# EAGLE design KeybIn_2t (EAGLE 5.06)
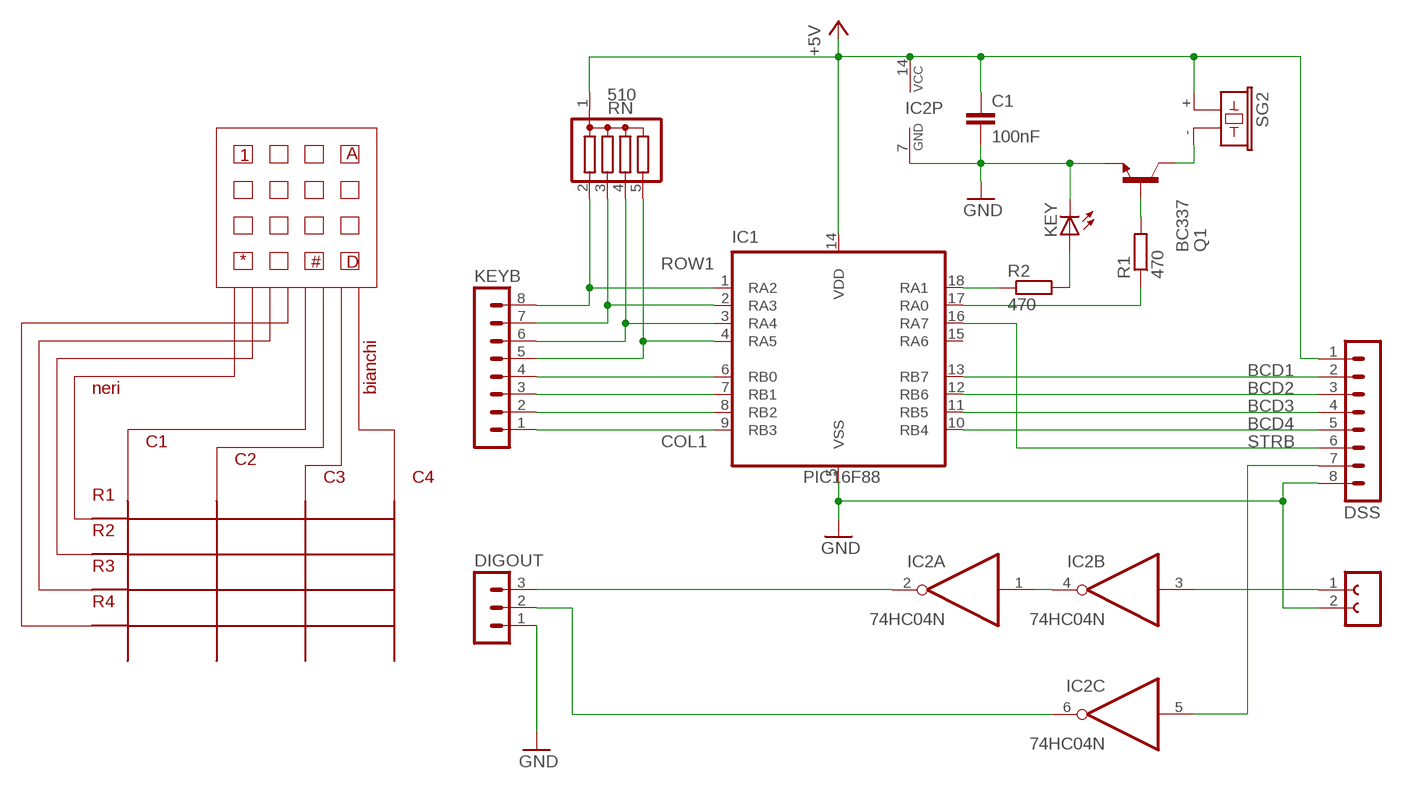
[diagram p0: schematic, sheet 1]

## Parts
510  RN  G04R  [SIL5]
C1  100nF  C-EU050-024X044  [C050-024X044]
DIGOUT  MA03-1  [MA03-1]
DSS  MA08-1  [MA08-1]
IC1  PIC16F88  [DIL18]
IC2  74HC04N  [DIL14]
KEY  LED3MM  [LED3MM]
KEYB  MA08-1  [MA08-1]
Q1  BC337  [TO92]
R1  470  R-EU_0204/7  [0204/7]
R2  470  R-EU_0204/7  [0204/7]
SG2  F/CM12P  [F/CM12P]
U$1  FE02-1  [FE-2]

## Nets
+5V: 510.1 C1.1 DSS.1 IC1.14(VDD) IC2.14(P:VCC) SG2.+
BCD1: DSS.2 IC1.13(RB7)
BCD2: DSS.3 IC1.12(RB6)
BCD3: DSS.4 IC1.11(RB5)
BCD4: DSS.5 IC1.10(RB4)
COL1: IC1.6(RB0) KEYB.4
DIG: DSS.8 IC1.5(VSS) U$1.2 ; supply symbol labelled GND
GND: C1.2 DIGOUT.1 IC2.7(P:GND) KEY.K(C) Q1.1(E)
N$1: IC1.17(RA0) R1.1
N$2: 510.3 IC1.2(RA3) KEYB.7
N$3: 510.4 IC1.3(RA4) KEYB.6
N$4: 510.5 IC1.4(RA5) KEYB.5
N$5: Q1.2(B) R1.2
N$6: IC1.9(RB3) KEYB.1
N$7: IC1.8(RB2) KEYB.2
N$8: IC1.7(RB1) KEYB.3
N$9: Q1.3(C) SG2.-
N$10: IC1.18(RA1) R2.1
N$11: IC2.1(A:I) IC2.4(B:O)
N$12: IC2.3(B:I) U$1.1
N$13: DIGOUT.3 IC2.2(A:O)
N$14: DIGOUT.2 IC2.6(C:O)
N$15: DSS.7 IC2.5(C:I)
N$17: KEY.A R2.2
ROW1: 510.2 IC1.1(RA2) KEYB.8
STRB: DSS.6 IC1.16(RA7)
Unconnected: IC1.15(RA6) IC2.8(D:O) IC2.9(D:I) IC2.10(E:O) IC2.11(E:I) IC2.12(F:O) IC2.13(F:I)

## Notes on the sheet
- 1 | A
- * | # | D
- neri | bianchi
- C1
- C2
- C3 | C4
- R1
- R2
- R3
- R4

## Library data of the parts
510 = resistor-sil:G04R: SIL RESISTOR
C1 = rcl:C-EU: CAPACITOR, European symbol
DIGOUT = con-lstb:MA03-1: PIN HEADER
DSS KEYB = con-lstb:MA08-1: PIN HEADER
IC1 = microchip-5:PIC16F88: 18 pin PDIP CPU - internal oscillator
IC2 = 74xx-eu:74*04: Hex INVERTER
KEY = led:LED: LED
Q1 = transistor-npn:BC337*: NPN Transistor
R1 R2 = rcl:R-EU_: RESISTOR, European symbol
SG2 = buzzer:F/CM12P: BUZZER
U$1 = con-lsta:FE02-1

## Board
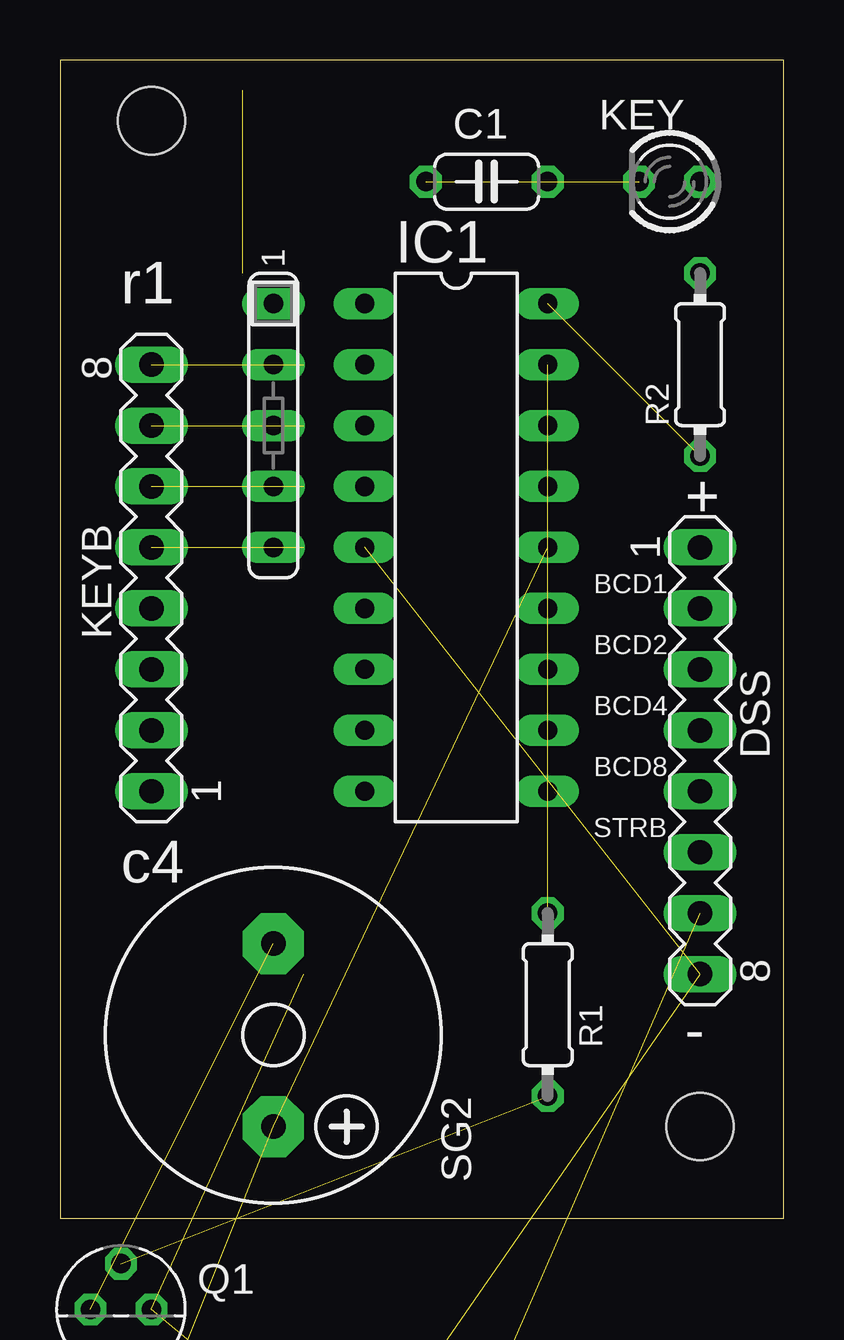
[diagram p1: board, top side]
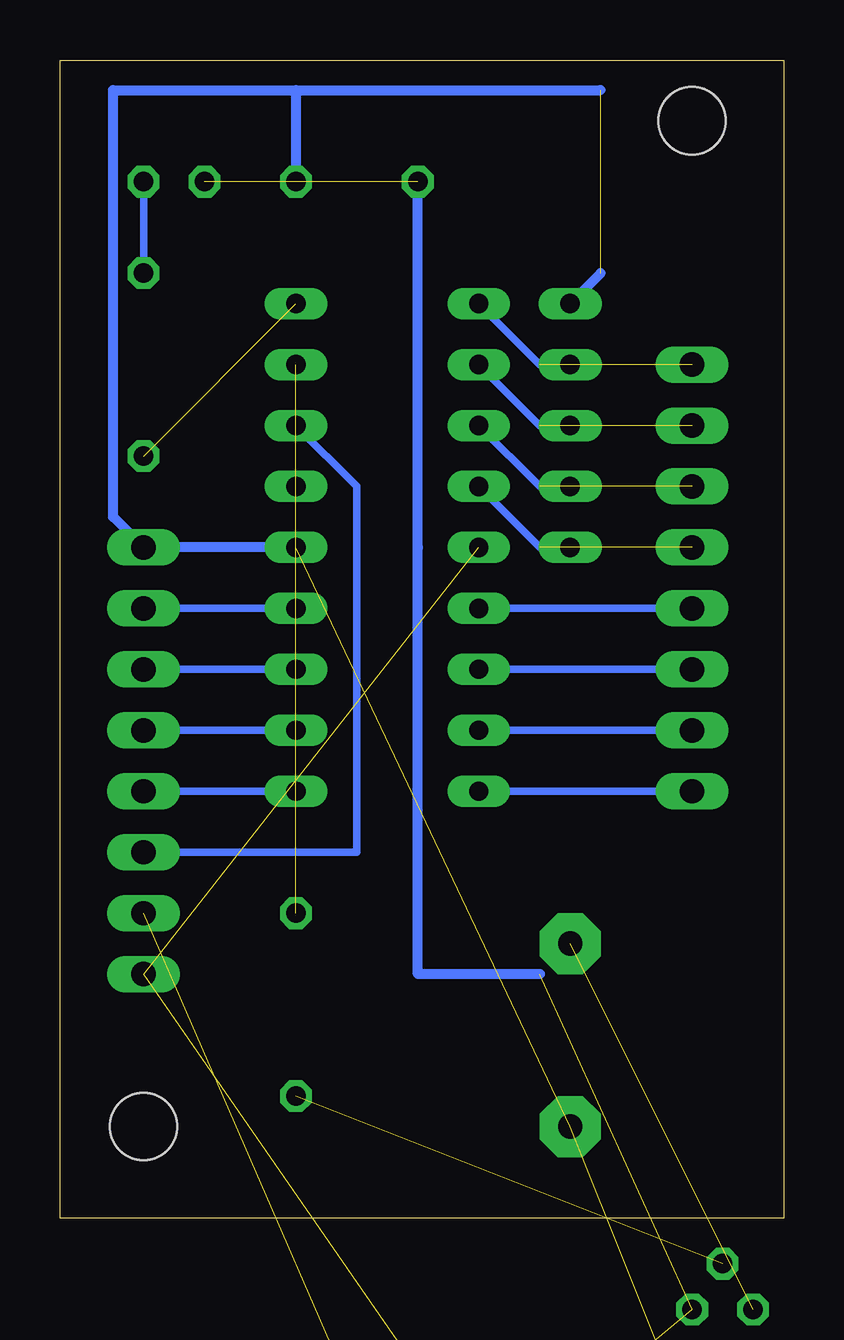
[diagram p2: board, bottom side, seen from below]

Size 30.15 x 48.25 mm. Coordinates in mm from the lower left corner, seen from the top.
Outline: 0,0 30.15,0 30.15,48.25 0,48.25 0,0
Copper layers (1*16): Top 0.035mm / dielectric 1.5mm / Bottom 0.035mm
Design rules "default": minimum track width 10mil, minimum drill 24mil, track to track 8mil, track to pad 8mil, pad to pad 8mil, via to via 8mil, smd to smd 8mil, copper to edge 40mil, drill to drill 8mil, minimum pad ring 10mil, minimum via ring 8mil, stop-mask expansion 4mil, vias tented up to drill 0mil, thermal gap 10mil
Holes 2.8 mm at 3.81,45.72 26.67,3.81

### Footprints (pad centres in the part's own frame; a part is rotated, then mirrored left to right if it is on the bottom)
SIL5 = drill 0.813 long: 1 -5.08,0; 2 -2.54,0; 3 0,0; 4 2.54,0; 5 5.08,0
C050-024X044 = drill 0.813 octagon: 1 -2.54,0; 2 2.54,0
MA03-1 = drill 1.016 long: 1 -2.54,0; 2 0,0; 3 2.54,0
MA08-1 = drill 1.016 long: 1 -8.89,0; 2 -6.35,0; 3 -3.81,0; 4 -1.27,0; 5 1.27,0; 6 3.81,0; 7 6.35,0; 8 8.89,0
DIL18 = drill 0.8 pad 1.27 long: 1 -10.16,-3.81; 2 -7.62,-3.81; 3 -5.08,-3.81; 4 -2.54,-3.81; 5 0,-3.81; 6 2.54,-3.81; 7 5.08,-3.81; 8 7.62,-3.81; 9 10.16,-3.81; 10 10.16,3.81; 11 7.62,3.81; 12 5.08,3.81; 13 2.54,3.81; 14 0,3.81; 15 -2.54,3.81; 16 -5.08,3.81; 17 -7.62,3.81; 18 -10.16,3.81
DIL14 = drill 0.813 long: 1 -7.62,-3.81; 2 -5.08,-3.81; 3 -2.54,-3.81; 4 0,-3.81; 5 2.54,-3.81; 6 5.08,-3.81; 7 7.62,-3.81; 8 7.62,3.81; 9 5.08,3.81; 10 2.54,3.81; 11 0,3.81; 12 -2.54,3.81; 13 -5.08,3.81; 14 -7.62,3.81
LED3MM = drill 0.813 octagon: A -1.27,0; K 1.27,0
TO92 = drill 0.813 octagon: 1 1.27,0; 2 0,1.905; 3 -1.27,0
0204/7 = drill 0.813 octagon: 1 -3.81,0; 2 3.81,0
F/CM12P = drill 1.016 pad 2.54 octagon: + 3.81,0; - -3.81,0
FE-2 = drill 1.1 long: 1 -10.16,1.27; 2 -7.62,1.27

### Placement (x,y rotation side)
510  8.89,33.02 270 top
C1  17.78,43.18 180 top
DIGOUT  not placed on the board
DSS  26.67,19.05 270 top
IC1  16.51,27.94 270 top
IC2  not placed on the board
KEY  25.4,43.18 180 top
KEYB  3.81,26.67 90 top
Q1  2.54,-3.81 0 top
R1  20.32,8.89 270 top
R2  26.67,35.56 90 top
SG2  8.89,7.62 270 top
U$1  not placed on the board

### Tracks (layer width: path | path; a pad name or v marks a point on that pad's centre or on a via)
+5V  (3 unrouted)
  Bottom 0.406: 7.62,39.37 510.1 | 20.32,46.99 7.62,46.99 | 20.32,46.99 27.94,46.99 27.94,31.75 27.94,29.21 DSS.1 IC1.14 | 20.32,46.99 C1.1
BCD1
  Bottom 0.305: IC1.13 DSS.2
BCD2
  Bottom 0.305: IC1.12 DSS.3
BCD3
  Bottom 0.305: IC1.11 DSS.4
BCD4
  Bottom 0.305: IC1.10 DSS.5
COL1
  Bottom 0.305: KEYB.4 IC1.6
DIG  (2 unrouted)
GND  (4 unrouted)
  Bottom 0.406: C1.2 15.24,27.94 15.24,10.16 10.16,10.16
N$1  (1 unrouted)
N$2  (2 unrouted)
  Bottom 0.305: 10.16,33.02 IC1.2
N$3  (2 unrouted)
  Bottom 0.305: 10.16,30.48 IC1.3
N$4  (2 unrouted)
  Bottom 0.305: 10.16,27.94 IC1.4
N$5  (1 unrouted)
N$6
  Bottom 0.305: KEYB.1 IC1.9
N$7
  Bottom 0.305: KEYB.2 IC1.8
N$8
  Bottom 0.305: KEYB.3 IC1.7
N$9  (1 unrouted)
N$10  (1 unrouted)
N$11  (1 unrouted)
N$12  (1 unrouted)
N$13  (1 unrouted)
N$14  (1 unrouted)
N$15  (1 unrouted)
N$17
  Bottom 0.305: R2.2 KEY.A
ROW1  (2 unrouted)
  Bottom 0.305: 10.16,35.56 IC1.1
STRB
  Bottom 0.305: IC1.16 17.78,30.48 17.78,15.24 DSS.6

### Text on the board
tNames: r1 | + | BCD1 | BCD2 | BCD4 | BCD8 | STRB | c4 | -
